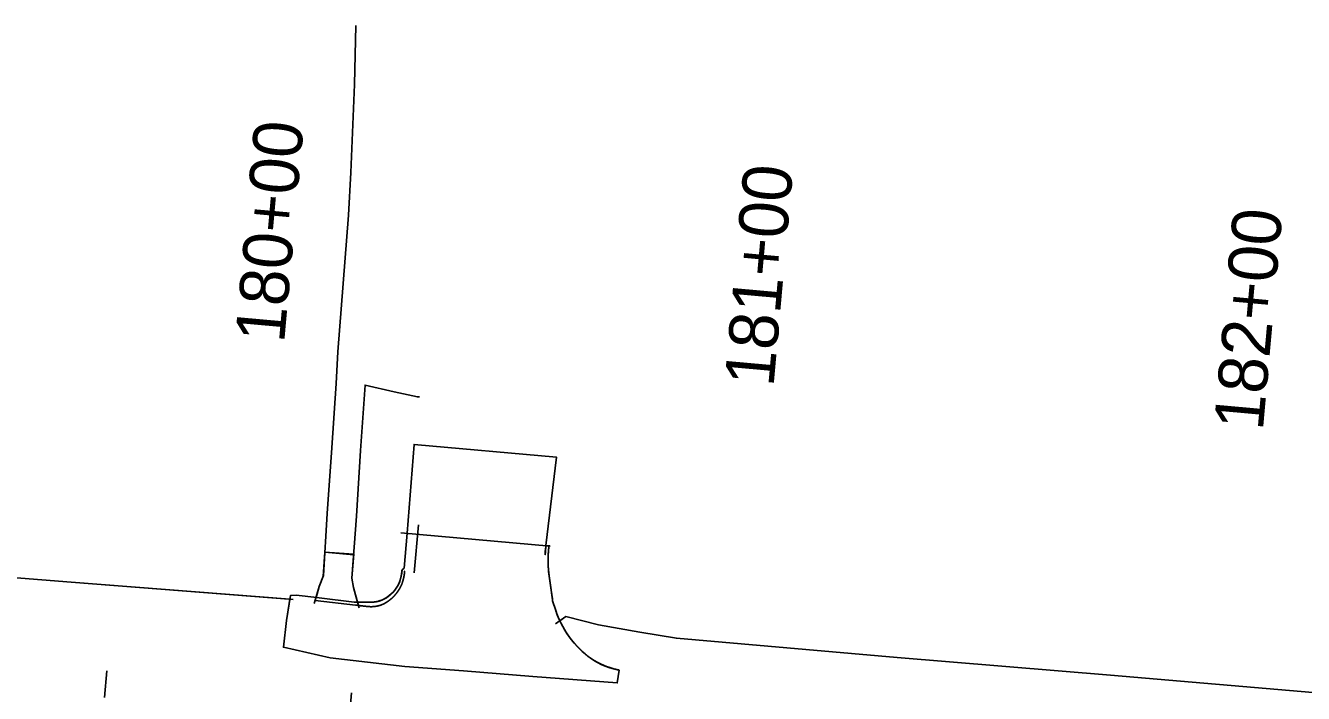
# Model space of a CAD drawing. Extents: x 20499880 to 20505309, y 7953507 to 7955507.
# Drawn here: x 20501667.8 to 20501927.9, y 7953902.7 to 7954038.7 of the extents above; entities that cross this region are included whole.
import ezdxf

# ---------------------------------------------------------------- set-up
doc = ezdxf.new("R2010")
doc.units = 0
for name, color, linetype in [('Alignment', 7, 'Continuous'), ('Curb', 7, 'Continuous'), ('Draft_0', 7, 'Continuous'), ('Entrance', 7, 'Continuous')]:
    doc.layers.add(name, color=color, linetype=linetype)

msp = doc.modelspace()

# ---------------------------------------------------------------- linework, layer by layer
at = {"layer": 'Curb'}
for p, q in [((20501746.96, 7953927.29), (20501747.84, 7953937.07)), ((20501774.63, 7953932.72), (20501744.21, 7953935.44)), ((20501728.75, 7953931.48), (20501728.43, 7953926.49)), ((20501728.75, 7953931.48), (20501734.63, 7953930.96)), ((20501720.95, 7953917.54), (20501721.75, 7953922.63)), ((20501722.89, 7953922.69), (20501721.75, 7953922.63)), ((20501727.15, 7953922.25), (20501722.89, 7953922.69)), ((20501727, 7953922.38), (20501726.61, 7953920.99)), ((20501727.6, 7953922.2), (20501727.15, 7953922.25)), ((20501734.7, 7953921.27), (20501727.6, 7953922.2)), ((20501735.32, 7953921.31), (20501734.7, 7953921.27)), ((20501735.36, 7953921.53), (20501735.75, 7953920.14)), ((20501775.12, 7953921.59), (20501775.74, 7953919.59)), ((20501720.32, 7953912.11), (20501720.95, 7953917.54)), ((20501729.83, 7953909.97), (20501720.32, 7953912.11)), ((20501745.01, 7953908.18), (20501729.83, 7953909.97)), ((20501757, 7953907.33), (20501745.01, 7953908.18)), ((20501771.09, 7953906.16), (20501757, 7953907.33)), ((20501788.64, 7953907.48), (20501788.27, 7953904.85)), ((20501788.27, 7953904.85), (20501771.09, 7953906.16))]:
    msp.add_line(p, q, dxfattribs=at)
for points in [[(20501727, 7953922.38), (20501727.58, 7953924.46), (20501728.45, 7953926.74), (20501729.25, 7953939.35), (20501730.16, 7953952.73), (20501731.06, 7953965.8), (20501731.42, 7953972.27), (20501733.6, 7954000.09), (20501734.05, 7954008.77), (20501734.82, 7954026.71), (20501735.06, 7954038.69)], [(20501735.36, 7953921.53), (20501734.58, 7953924.3), (20501734.28, 7953926.16), (20501735.19, 7953938.78), (20501736.04, 7953952.15), (20501736.96, 7953965.5), (20501742.85, 7953964.12), (20501747.58, 7953963.08), (20501748.05, 7953963.1)], [(20501722.29, 7953921.85), (20501677.12, 7953925.34), (20501650.59, 7953927.49), (20501645.85, 7953925.21), (20501633.38, 7953926.32), (20501609.89, 7953928.7), (20501589.06, 7953931.11), (20501540.94, 7953935.13), (20501510.62, 7953937.62), (20501495.91, 7953940.76), (20501455.36, 7953944.15), (20501410.85, 7953947.34), (20501367.41, 7953950.44)], [(20501744.46, 7953927.89), (20501744.91, 7953928.22), (20501745.52, 7953935.32)], [(20502508.71, 7953854.1), (20502476.24, 7953857.13), (20502433.37, 7953860.92), (20502388.38, 7953864.8), (20502343.12, 7953868.7), (20502295.63, 7953872.96), (20502250.52, 7953876.88), (20502202.15, 7953880.25), (20502156.92, 7953883.72), (20502112.34, 7953886.91), (20502066.45, 7953889.96), (20502020.52, 7953893.42), (20501974.76, 7953896.96), (20501963.75, 7953897.64), (20501941.91, 7953902.08), (20501932.22, 7953902.73), (20501888.64, 7953906.43), (20501845.21, 7953910.05), (20501800.31, 7953913.93), (20501792.88, 7953915.17), (20501784.48, 7953916.66), (20501777.79, 7953918.36), (20501775.73, 7953916.88)]]:
    msp.add_lwpolyline(points, dxfattribs=at)
for points in [[(20501774.4, 7953932.91), (20501774.24, 7953931.69), (20501774.05, 7953928.95), (20501774.63, 7953925.18), (20501774.96, 7953922.64), (20501775.12, 7953921.59)], [(20501744.46, 7953927.89), (20501744.32, 7953926.03), (20501743.36, 7953923.54), (20501739.6, 7953920.9), (20501736.69, 7953921.38), (20501735.32, 7953921.31)], [(20501775.74, 7953919.59), (20501776.56, 7953917.24), (20501778.75, 7953913.35), (20501783.46, 7953908.99), (20501787, 7953907.79), (20501788.64, 7953907.48)]]:
    msp.add_open_spline(points, degree=3, dxfattribs=at)
at = {"layer": 'Draft_0'}
for p, q in [((20501773.74, 7953932.8), (20501774.38, 7953932.74)), ((20501775.12, 7953921.59), (20501775.74, 7953919.59))]:
    msp.add_line(p, q, dxfattribs=at)
for points in [[(20501744.46, 7953927.89), (20501744.91, 7953928.22), (20501745.52, 7953935.32), (20501746.91, 7953953.41), (20501775.93, 7953950.79), (20501773.74, 7953932.8)], [(20501367.41, 7953950.44), (20501410.85, 7953947.34), (20501455.36, 7953944.15), (20501495.91, 7953940.76), (20501510.62, 7953937.62), (20501540.94, 7953935.13), (20501589.06, 7953931.11), (20501609.89, 7953928.7), (20501633.38, 7953926.32), (20501645.85, 7953925.21), (20501650.59, 7953927.49), (20501677.12, 7953925.34), (20501721.64, 7953921.9), (20501720.95, 7953917.54), (20501720.32, 7953912.11), (20501729.83, 7953909.97), (20501745.01, 7953908.18), (20501757, 7953907.33), (20501771.09, 7953906.16), (20501788.27, 7953904.85), (20501788.64, 7953907.48)], [(20501735.32, 7953921.31), (20501734.7, 7953921.27), (20501727.6, 7953922.2), (20501727.15, 7953922.25), (20501726.97, 7953922.27), (20501727.58, 7953924.46), (20501728.45, 7953926.74), (20501728.75, 7953931.48), (20501734.63, 7953931.06), (20501734.28, 7953926.16), (20501734.58, 7953924.3), (20501735.42, 7953921.31)], [(20501788.64, 7953907.48), (20501788.27, 7953904.85), (20501771.09, 7953906.16), (20501757, 7953907.33), (20501745.01, 7953908.18), (20501729.83, 7953909.97), (20501720.32, 7953912.11), (20501720.95, 7953917.54), (20501721.75, 7953922.63), (20501722.89, 7953922.69), (20501727.15, 7953922.25), (20501727.6, 7953922.2), (20501734.7, 7953921.27), (20501735.32, 7953921.31)], [(20501734.99, 7953920.69), (20501726.79, 7953921.6), (20501726.78, 7953921.6), (20501726.79, 7953921.6), (20501734.99, 7953920.69)], [(20501776.59, 7953917.5), (20501777.79, 7953918.36), (20501784.48, 7953916.66), (20501792.88, 7953915.17), (20501800.31, 7953913.93), (20501845.21, 7953910.05), (20501888.64, 7953906.43), (20501932.22, 7953902.73)]]:
    msp.add_lwpolyline(points, dxfattribs=at)
for points in [[(20501773.61, 7953930.96), (20501773.59, 7953931.53), (20501773.68, 7953932.13), (20501773.72, 7953932.52)], [(20501773.74, 7953932.8), (20501773.61, 7953930.94), (20501773.61, 7953930.95), (20501773.61, 7953930.96)], [(20501773.72, 7953932.52), (20501773.73, 7953932.62), (20501773.74, 7953932.71), (20501773.74, 7953932.8)], [(20501774.21, 7953930.89), (20501774.2, 7953930.77), (20501774.2, 7953930.65), (20501774.19, 7953930.53)], [(20501774.19, 7953930.53), (20501774.19, 7953930.47), (20501774.19, 7953930.4), (20501774.19, 7953930.34)], [(20501774.33, 7953932.36), (20501774.28, 7953931.87), (20501774.24, 7953931.38), (20501774.21, 7953930.89)], [(20501774.38, 7953932.74), (20501774.36, 7953932.61), (20501774.35, 7953932.49), (20501774.33, 7953932.36)], [(20501774.19, 7953930.34), (20501774.18, 7953929.98), (20501774.18, 7953929.61), (20501774.19, 7953929.24)], [(20501774.19, 7953929.24), (20501774.2, 7953929.02), (20501774.21, 7953928.79), (20501774.22, 7953928.57)], [(20501774.22, 7953928.57), (20501774.25, 7953928.19), (20501774.28, 7953927.81), (20501774.32, 7953927.44)], [(20501743.74, 7953924.96), (20501743.84, 7953925.17), (20501743.93, 7953925.39), (20501744.01, 7953925.62)], [(20501743.97, 7953924.06), (20501744.26, 7953924.58), (20501744.49, 7953925.12), (20501744.66, 7953925.71)], [(20501744.66, 7953925.71), (20501744.49, 7953925.12), (20501744.26, 7953924.58), (20501743.97, 7953924.06)], [(20501744.01, 7953925.62), (20501744.09, 7953925.84), (20501744.16, 7953926.08), (20501744.22, 7953926.32)], [(20501744.22, 7953926.32), (20501744.26, 7953926.48), (20501744.29, 7953926.65), (20501744.32, 7953926.82)], [(20501744.32, 7953926.82), (20501744.34, 7953926.91), (20501744.35, 7953926.99), (20501744.37, 7953927.08)], [(20501744.37, 7953927.08), (20501744.38, 7953927.17), (20501744.39, 7953927.25), (20501744.4, 7953927.34)], [(20501744.4, 7953927.34), (20501744.43, 7953927.52), (20501744.45, 7953927.7), (20501744.46, 7953927.89)], [(20501744.66, 7953925.71), (20501744.68, 7953925.79), (20501744.7, 7953925.86), (20501744.72, 7953925.94)], [(20501744.72, 7953925.94), (20501744.7, 7953925.86), (20501744.68, 7953925.79), (20501744.66, 7953925.71)], [(20501744.72, 7953925.94), (20501744.74, 7953926.01), (20501744.76, 7953926.09), (20501744.78, 7953926.16)], [(20501744.78, 7953926.16), (20501744.76, 7953926.09), (20501744.74, 7953926.01), (20501744.72, 7953925.94)], [(20501744.78, 7953926.16), (20501744.79, 7953926.24), (20501744.81, 7953926.31), (20501744.83, 7953926.39)], [(20501744.83, 7953926.39), (20501744.81, 7953926.31), (20501744.79, 7953926.24), (20501744.78, 7953926.16)], [(20501744.83, 7953926.39), (20501744.84, 7953926.47), (20501744.86, 7953926.55), (20501744.87, 7953926.63)], [(20501744.87, 7953926.63), (20501744.86, 7953926.55), (20501744.84, 7953926.47), (20501744.83, 7953926.39)], [(20501744.87, 7953926.63), (20501744.93, 7953926.94), (20501744.97, 7953927.27), (20501745, 7953927.61)], [(20501745, 7953927.61), (20501744.97, 7953927.27), (20501744.93, 7953926.94), (20501744.87, 7953926.63)], [(20501774.32, 7953927.44), (20501774.4, 7953926.68), (20501774.51, 7953925.93), (20501774.62, 7953925.18)], [(20501741.95, 7953922.67), (20501741.99, 7953922.71), (20501742.04, 7953922.75), (20501742.08, 7953922.79)], [(20501742.08, 7953922.79), (20501742.13, 7953922.83), (20501742.17, 7953922.87), (20501742.21, 7953922.9)], [(20501742.21, 7953922.9), (20501742.26, 7953922.94), (20501742.3, 7953922.98), (20501742.34, 7953923.02)], [(20501742.34, 7953923.02), (20501742.42, 7953923.1), (20501742.51, 7953923.19), (20501742.58, 7953923.27)], [(20501742.58, 7953923.27), (20501742.62, 7953923.31), (20501742.66, 7953923.36), (20501742.7, 7953923.4)], [(20501742.7, 7953923.4), (20501742.81, 7953923.52), (20501742.91, 7953923.64), (20501743, 7953923.76)], [(20501742.74, 7953922.44), (20501742.85, 7953922.55), (20501742.95, 7953922.66), (20501743.05, 7953922.78)], [(20501743.05, 7953922.78), (20501742.95, 7953922.66), (20501742.85, 7953922.55), (20501742.74, 7953922.44)], [(20501743, 7953923.76), (20501743.15, 7953923.95), (20501743.28, 7953924.14), (20501743.4, 7953924.34)], [(20501743.05, 7953922.78), (20501743.2, 7953922.95), (20501743.34, 7953923.12), (20501743.47, 7953923.3)], [(20501743.47, 7953923.3), (20501743.34, 7953923.12), (20501743.2, 7953922.95), (20501743.05, 7953922.78)], [(20501743.4, 7953924.34), (20501743.52, 7953924.54), (20501743.63, 7953924.74), (20501743.74, 7953924.96)], [(20501743.47, 7953923.3), (20501743.52, 7953923.36), (20501743.56, 7953923.42), (20501743.6, 7953923.48)], [(20501743.6, 7953923.48), (20501743.56, 7953923.42), (20501743.52, 7953923.36), (20501743.47, 7953923.3)], [(20501743.6, 7953923.48), (20501743.65, 7953923.55), (20501743.69, 7953923.61), (20501743.73, 7953923.67)], [(20501743.73, 7953923.67), (20501743.69, 7953923.61), (20501743.65, 7953923.55), (20501743.6, 7953923.48)], [(20501743.73, 7953923.67), (20501743.77, 7953923.74), (20501743.81, 7953923.8), (20501743.85, 7953923.86)], [(20501743.85, 7953923.86), (20501743.81, 7953923.8), (20501743.77, 7953923.74), (20501743.73, 7953923.67)], [(20501743.85, 7953923.86), (20501743.89, 7953923.93), (20501743.93, 7953923.99), (20501743.97, 7953924.06)], [(20501743.97, 7953924.06), (20501743.93, 7953923.99), (20501743.89, 7953923.93), (20501743.85, 7953923.86)], [(20501774.62, 7953925.18), (20501774.64, 7953925.03), (20501774.66, 7953924.88), (20501774.68, 7953924.73)], [(20501774.68, 7953924.73), (20501774.69, 7953924.68), (20501774.69, 7953924.62), (20501774.7, 7953924.57)], [(20501774.7, 7953924.57), (20501774.71, 7953924.52), (20501774.72, 7953924.47), (20501774.72, 7953924.41)], [(20501774.72, 7953924.41), (20501774.73, 7953924.36), (20501774.74, 7953924.31), (20501774.75, 7953924.26)], [(20501774.75, 7953924.26), (20501774.75, 7953924.21), (20501774.76, 7953924.15), (20501774.77, 7953924.1)], [(20501774.77, 7953924.1), (20501774.77, 7953924.05), (20501774.78, 7953924), (20501774.79, 7953923.94)], [(20501774.79, 7953923.94), (20501774.79, 7953923.89), (20501774.8, 7953923.84), (20501774.81, 7953923.79)], [(20501774.81, 7953923.79), (20501774.86, 7953923.42), (20501774.91, 7953923.05), (20501774.96, 7953922.69)], [(20501735.62, 7953920.62), (20501735.41, 7953920.65), (20501735.2, 7953920.67), (20501734.99, 7953920.69)], [(20501734.99, 7953920.69), (20501735.2, 7953920.67), (20501735.41, 7953920.65), (20501735.62, 7953920.62)], [(20501735.32, 7953921.31), (20501735.35, 7953921.31), (20501735.39, 7953921.31), (20501735.42, 7953921.31)], [(20501735.42, 7953921.31), (20501735.39, 7953921.31), (20501735.35, 7953921.31), (20501735.32, 7953921.31)], [(20501735.42, 7953921.31), (20501735.46, 7953921.31), (20501735.49, 7953921.31), (20501735.53, 7953921.31)], [(20501735.53, 7953921.31), (20501736.16, 7953921.33), (20501736.83, 7953921.29), (20501737.52, 7953921.29)], [(20501736.63, 7953920.5), (20501736.3, 7953920.53), (20501735.97, 7953920.58), (20501735.62, 7953920.62)], [(20501735.62, 7953920.62), (20501735.97, 7953920.58), (20501736.3, 7953920.53), (20501736.63, 7953920.5)], [(20501736.89, 7953920.47), (20501736.8, 7953920.48), (20501736.72, 7953920.49), (20501736.63, 7953920.5)], [(20501736.63, 7953920.5), (20501736.72, 7953920.49), (20501736.8, 7953920.48), (20501736.89, 7953920.47)], [(20501739.07, 7953920.44), (20501738.38, 7953920.35), (20501737.66, 7953920.39), (20501736.89, 7953920.47)], [(20501736.89, 7953920.47), (20501737.66, 7953920.39), (20501738.38, 7953920.35), (20501739.07, 7953920.44)], [(20501737.52, 7953921.29), (20501737.6, 7953921.28), (20501737.67, 7953921.28), (20501737.75, 7953921.28)], [(20501737.75, 7953921.28), (20501737.83, 7953921.28), (20501737.9, 7953921.29), (20501737.98, 7953921.29)], [(20501737.98, 7953921.29), (20501738.06, 7953921.29), (20501738.13, 7953921.29), (20501738.21, 7953921.29)], [(20501738.21, 7953921.29), (20501738.29, 7953921.3), (20501738.36, 7953921.3), (20501738.44, 7953921.3)], [(20501738.44, 7953921.3), (20501738.75, 7953921.32), (20501739.05, 7953921.35), (20501739.35, 7953921.41)], [(20501739.3, 7953920.48), (20501739.23, 7953920.46), (20501739.15, 7953920.45), (20501739.07, 7953920.44)], [(20501739.07, 7953920.44), (20501739.15, 7953920.45), (20501739.23, 7953920.46), (20501739.3, 7953920.48)], [(20501739.53, 7953920.52), (20501739.46, 7953920.5), (20501739.38, 7953920.49), (20501739.3, 7953920.48)], [(20501739.3, 7953920.48), (20501739.38, 7953920.49), (20501739.46, 7953920.5), (20501739.53, 7953920.52)], [(20501739.35, 7953921.41), (20501739.42, 7953921.42), (20501739.5, 7953921.44), (20501739.57, 7953921.46)], [(20501739.76, 7953920.58), (20501739.69, 7953920.56), (20501739.61, 7953920.54), (20501739.53, 7953920.52)], [(20501739.53, 7953920.52), (20501739.61, 7953920.54), (20501739.69, 7953920.56), (20501739.76, 7953920.58)], [(20501739.57, 7953921.46), (20501739.64, 7953921.47), (20501739.72, 7953921.49), (20501739.79, 7953921.51)], [(20501739.99, 7953920.64), (20501739.91, 7953920.62), (20501739.84, 7953920.6), (20501739.76, 7953920.58)], [(20501739.76, 7953920.58), (20501739.84, 7953920.6), (20501739.91, 7953920.62), (20501739.99, 7953920.64)], [(20501739.79, 7953921.51), (20501740.07, 7953921.59), (20501740.35, 7953921.7), (20501740.61, 7953921.82)], [(20501740.19, 7953920.71), (20501740.12, 7953920.69), (20501740.06, 7953920.66), (20501739.99, 7953920.64)], [(20501739.99, 7953920.64), (20501740.06, 7953920.66), (20501740.12, 7953920.69), (20501740.19, 7953920.71)], [(20501740.58, 7953920.88), (20501740.45, 7953920.81), (20501740.32, 7953920.76), (20501740.19, 7953920.71)], [(20501740.19, 7953920.71), (20501740.32, 7953920.76), (20501740.45, 7953920.81), (20501740.58, 7953920.88)], [(20501740.78, 7953920.97), (20501740.71, 7953920.94), (20501740.65, 7953920.91), (20501740.58, 7953920.88)], [(20501740.58, 7953920.88), (20501740.65, 7953920.91), (20501740.71, 7953920.94), (20501740.78, 7953920.97)], [(20501740.61, 7953921.82), (20501740.67, 7953921.84), (20501740.72, 7953921.87), (20501740.77, 7953921.9)], [(20501740.77, 7953921.9), (20501741.19, 7953922.11), (20501741.59, 7953922.37), (20501741.95, 7953922.67)], [(20501741.16, 7953921.18), (20501741.03, 7953921.11), (20501740.91, 7953921.03), (20501740.78, 7953920.97)], [(20501740.78, 7953920.97), (20501740.91, 7953921.03), (20501741.03, 7953921.11), (20501741.16, 7953921.18)], [(20501741.35, 7953921.3), (20501741.29, 7953921.26), (20501741.22, 7953921.22), (20501741.16, 7953921.18)], [(20501741.16, 7953921.18), (20501741.22, 7953921.22), (20501741.29, 7953921.26), (20501741.35, 7953921.3)], [(20501741.72, 7953921.55), (20501741.6, 7953921.46), (20501741.47, 7953921.38), (20501741.35, 7953921.3)], [(20501741.35, 7953921.3), (20501741.47, 7953921.38), (20501741.6, 7953921.46), (20501741.72, 7953921.55)], [(20501741.9, 7953921.69), (20501741.84, 7953921.64), (20501741.78, 7953921.6), (20501741.72, 7953921.55)], [(20501741.72, 7953921.55), (20501741.78, 7953921.6), (20501741.84, 7953921.64), (20501741.9, 7953921.69)], [(20501742.08, 7953921.83), (20501742.02, 7953921.78), (20501741.96, 7953921.73), (20501741.9, 7953921.69)], [(20501741.9, 7953921.69), (20501741.96, 7953921.73), (20501742.02, 7953921.78), (20501742.08, 7953921.83)], [(20501742.42, 7953922.13), (20501742.31, 7953922.02), (20501742.19, 7953921.93), (20501742.08, 7953921.83)], [(20501742.08, 7953921.83), (20501742.19, 7953921.93), (20501742.31, 7953922.02), (20501742.42, 7953922.13)], [(20501742.74, 7953922.44), (20501742.64, 7953922.34), (20501742.53, 7953922.23), (20501742.42, 7953922.13)], [(20501742.42, 7953922.13), (20501742.53, 7953922.23), (20501742.64, 7953922.34), (20501742.74, 7953922.44)], [(20501774.96, 7953922.69), (20501775, 7953922.37), (20501775.05, 7953922.06), (20501775.1, 7953921.75)], [(20501775.1, 7953921.75), (20501775.1, 7953921.7), (20501775.11, 7953921.64), (20501775.12, 7953921.59)], [(20501775.74, 7953919.59), (20501775.82, 7953919.35), (20501775.91, 7953919.12), (20501776, 7953918.89)], [(20501776, 7953918.89), (20501776.04, 7953918.78), (20501776.09, 7953918.66), (20501776.13, 7953918.55)], [(20501776.13, 7953918.55), (20501776.18, 7953918.44), (20501776.23, 7953918.32), (20501776.27, 7953918.21)], [(20501776.27, 7953918.21), (20501776.37, 7953917.99), (20501776.47, 7953917.77), (20501776.57, 7953917.55)], [(20501776.57, 7953917.55), (20501776.62, 7953917.44), (20501776.67, 7953917.34), (20501776.72, 7953917.23)], [(20501776.72, 7953917.23), (20501776.68, 7953917.32), (20501776.64, 7953917.41), (20501776.59, 7953917.5)], [(20501776.89, 7953916.91), (20501776.83, 7953917.01), (20501776.78, 7953917.12), (20501776.72, 7953917.23)], [(20501776.72, 7953917.23), (20501776.78, 7953917.12), (20501776.83, 7953917.01), (20501776.89, 7953916.91)], [(20501777.22, 7953916.28), (20501777.11, 7953916.49), (20501776.99, 7953916.7), (20501776.89, 7953916.91)], [(20501776.89, 7953916.91), (20501776.99, 7953916.7), (20501777.11, 7953916.49), (20501777.22, 7953916.28)], [(20501777.4, 7953915.97), (20501777.34, 7953916.07), (20501777.28, 7953916.18), (20501777.22, 7953916.28)], [(20501777.22, 7953916.28), (20501777.28, 7953916.18), (20501777.34, 7953916.07), (20501777.4, 7953915.97)], [(20501777.58, 7953915.67), (20501777.52, 7953915.77), (20501777.46, 7953915.87), (20501777.4, 7953915.97)], [(20501777.4, 7953915.97), (20501777.46, 7953915.87), (20501777.52, 7953915.77), (20501777.58, 7953915.67)], [(20501777.76, 7953915.37), (20501777.7, 7953915.47), (20501777.64, 7953915.57), (20501777.58, 7953915.67)], [(20501777.58, 7953915.67), (20501777.82, 7953915.26), (20501778.08, 7953914.87), (20501778.35, 7953914.48)], [(20501778.15, 7953914.77), (20501778.02, 7953914.97), (20501777.89, 7953915.17), (20501777.76, 7953915.37)], [(20501778.35, 7953914.48), (20501778.28, 7953914.58), (20501778.22, 7953914.68), (20501778.15, 7953914.77)], [(20501779.21, 7953913.35), (20501778.91, 7953913.72), (20501778.62, 7953914.1), (20501778.35, 7953914.48)], [(20501778.35, 7953914.48), (20501778.42, 7953914.39), (20501778.49, 7953914.29), (20501778.56, 7953914.19)], [(20501778.56, 7953914.19), (20501778.77, 7953913.91), (20501778.99, 7953913.62), (20501779.21, 7953913.35)], [(20501779.42, 7953913.1), (20501779.35, 7953913.18), (20501779.28, 7953913.26), (20501779.21, 7953913.35)], [(20501779.21, 7953913.35), (20501779.28, 7953913.26), (20501779.35, 7953913.18), (20501779.42, 7953913.1)], [(20501779.63, 7953912.85), (20501779.56, 7953912.93), (20501779.49, 7953913.01), (20501779.42, 7953913.1)], [(20501779.42, 7953913.1), (20501779.49, 7953913.01), (20501779.56, 7953912.93), (20501779.63, 7953912.85)], [(20501779.84, 7953912.6), (20501779.77, 7953912.68), (20501779.7, 7953912.76), (20501779.63, 7953912.85)], [(20501779.63, 7953912.85), (20501779.7, 7953912.76), (20501779.77, 7953912.68), (20501779.84, 7953912.6)], [(20501780.06, 7953912.36), (20501779.99, 7953912.44), (20501779.92, 7953912.52), (20501779.84, 7953912.6)], [(20501779.84, 7953912.6), (20501779.92, 7953912.52), (20501779.99, 7953912.44), (20501780.06, 7953912.36)], [(20501780.29, 7953912.12), (20501780.21, 7953912.2), (20501780.14, 7953912.28), (20501780.06, 7953912.36)], [(20501780.06, 7953912.36), (20501780.14, 7953912.28), (20501780.21, 7953912.2), (20501780.29, 7953912.12)], [(20501781.22, 7953911.2), (20501780.9, 7953911.49), (20501780.59, 7953911.8), (20501780.29, 7953912.12)], [(20501780.29, 7953912.12), (20501780.36, 7953912.04), (20501780.44, 7953911.96), (20501780.51, 7953911.88)], [(20501780.51, 7953911.88), (20501780.67, 7953911.73), (20501780.82, 7953911.57), (20501780.98, 7953911.42)], [(20501780.98, 7953911.42), (20501781.06, 7953911.35), (20501781.14, 7953911.27), (20501781.22, 7953911.2)], [(20501781.46, 7953910.98), (20501781.38, 7953911.05), (20501781.3, 7953911.12), (20501781.22, 7953911.2)], [(20501781.22, 7953911.2), (20501781.46, 7953910.97), (20501781.71, 7953910.76), (20501781.96, 7953910.55)], [(20501782.48, 7953910.15), (20501782.13, 7953910.41), (20501781.79, 7953910.69), (20501781.46, 7953910.98)], [(20501781.96, 7953910.55), (20501782.64, 7953910), (20501783.35, 7953909.5), (20501784.1, 7953909.08)], [(20501783, 7953909.77), (20501782.83, 7953909.89), (20501782.65, 7953910.02), (20501782.48, 7953910.15)], [(20501784.1, 7953909.08), (20501783.73, 7953909.29), (20501783.36, 7953909.52), (20501783, 7953909.77)], [(20501784.31, 7953908.97), (20501784.24, 7953909), (20501784.17, 7953909.04), (20501784.1, 7953909.08)], [(20501784.1, 7953909.08), (20501784.79, 7953908.69), (20501785.52, 7953908.37), (20501786.27, 7953908.11)], [(20501784.73, 7953908.75), (20501784.59, 7953908.82), (20501784.45, 7953908.89), (20501784.31, 7953908.97)], [(20501784.95, 7953908.65), (20501784.88, 7953908.68), (20501784.8, 7953908.71), (20501784.73, 7953908.75)], [(20501786.73, 7953907.95), (20501786.12, 7953908.15), (20501785.52, 7953908.38), (20501784.95, 7953908.65)], [(20501786.27, 7953908.11), (20501786.35, 7953908.08), (20501786.43, 7953908.05), (20501786.5, 7953908.03)], [(20501786.5, 7953908.03), (20501786.58, 7953908), (20501786.66, 7953907.98), (20501786.73, 7953907.95)], [(20501787.43, 7953907.75), (20501787.2, 7953907.81), (20501786.96, 7953907.88), (20501786.73, 7953907.95)], [(20501786.73, 7953907.95), (20501787.12, 7953907.83), (20501787.51, 7953907.73), (20501787.91, 7953907.63)], [(20501787.67, 7953907.69), (20501787.59, 7953907.71), (20501787.51, 7953907.73), (20501787.43, 7953907.75)], [(20501788.39, 7953907.53), (20501788.15, 7953907.58), (20501787.91, 7953907.63), (20501787.67, 7953907.69)], [(20501787.91, 7953907.63), (20501787.99, 7953907.61), (20501788.07, 7953907.59), (20501788.15, 7953907.58)], [(20501788.15, 7953907.58), (20501788.23, 7953907.56), (20501788.31, 7953907.54), (20501788.39, 7953907.53)], [(20501788.64, 7953907.48), (20501788.56, 7953907.49), (20501788.48, 7953907.51), (20501788.39, 7953907.53)], [(20501788.39, 7953907.53), (20501788.48, 7953907.51), (20501788.56, 7953907.49), (20501788.64, 7953907.48)]]:
    msp.add_open_spline(points, degree=2, dxfattribs=at)
at = {"layer": 'Entrance'}
for p, q in [((20501683.88, 7953901.87), (20501684.37, 7953907.3)), ((20501733.68, 7953897.41), (20501734.17, 7953902.84))]:
    msp.add_line(p, q, dxfattribs=at)

# ---------------------------------------------------------------- texts
at = {"layer": 'Alignment'}
msp.add_text('180+00', height=10.02, rotation=84.8834, dxfattribs=at).set_placement((20501720.46, 7953973.89))
at = {"layer": 'Entrance'}
for s, p in [('180+00', (20501720.46, 7953973.89)), ('181+00', (20501820.06, 7953964.97)), ('182+00', (20501919.66, 7953956.05))]:
    msp.add_text(s, height=10.02, rotation=84.8834, dxfattribs=at).set_placement(p)

doc.saveas('drawing.dxf')
